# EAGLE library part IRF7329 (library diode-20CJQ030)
International Rectifier's IRF7329 HEXFET® Power MOSFET Description: Features: Trench Technology Ultra Low On-Resistance Dual P-Channel MOSFET Low Profile ( Please send any comments to: messi@users.sourceforge.net
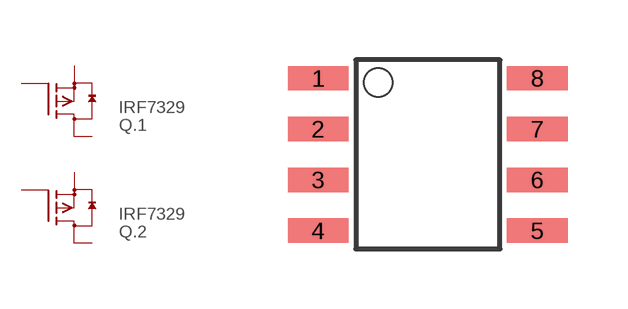
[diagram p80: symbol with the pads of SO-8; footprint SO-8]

Designator prefix Q; gates .1=IGFET-4-P-CH .2=IGFET-4-P-CH

## IRF7329  [SO-8]
1  .1:S  pas
2  .1:G  pas
3  .2:S  pas
4  .2:G  pas
5  .2:D  pas
6  .2:D  pas
7  .1:D  pas
8  .1:D  pas

## Footprint SO-8 (pad centres in mm)
small outline
smd 1.524 x 0.61: 1 -2.743,1.27; 2 -2.743,0; 3 -2.743,-1.27; 4 -2.743,-2.54; 5 2.743,-2.54; 6 2.743,-1.27; 7 2.743,0; 8 2.743,1.27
